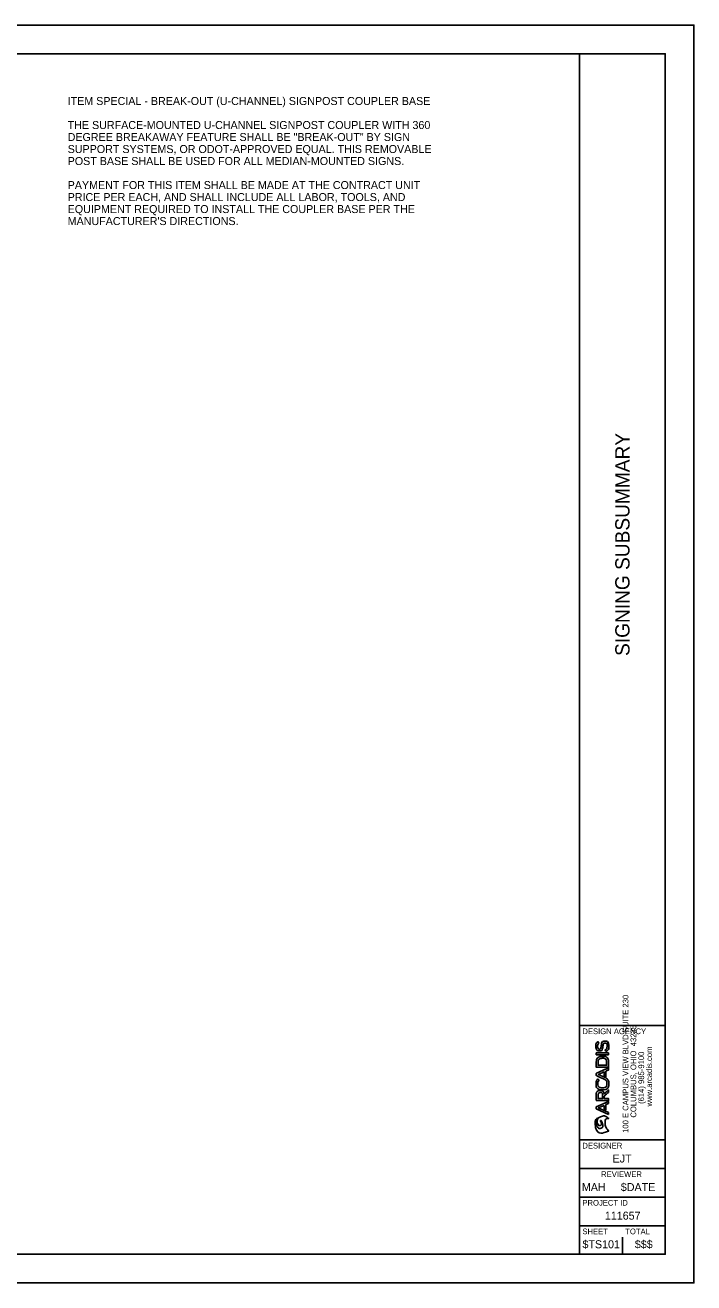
# Model space of a CAD drawing. Extents: x 0 to 34, y 0 to 22.
# Drawn here: x 22.3 to 34, y 0 to 22 of the extents above; entities that cross this region are included whole.
import ezdxf

# ---------------------------------------------------------------- set-up
doc = ezdxf.new("R2010")
doc.units = 0
for name, color, linetype in [('SH_Border', 7, 'Continuous'), ('SH_Cut_Line', 7, 'Continuous'), ('SH_Data', 7, 'Continuous'), ('SH_Text', 7, 'Continuous')]:
    doc.layers.add(name, color=color, linetype=linetype)

msp = doc.modelspace()

# ---------------------------------------------------------------- linework, layer by layer
at = {"layer": 'SH_Border'}
for p, q in [((32, 0.5), (32, 21.5)), ((32, 4.5), (33.5, 4.5)), ((32, 2.5), (33.5, 2.5)), ((32, 2), (33.5, 2)), ((32, 1.5), (33.5, 1.5)), ((32, 1), (33.5, 1))]:
    msp.add_line(p, q, dxfattribs=at)
msp.add_lwpolyline([(1.5, 21.5), (33.5, 21.5), (33.5, 0.5), (1.5, 0.5)], close=True, dxfattribs=at)
at = {"layer": 'SH_Cut_Line'}
msp.add_lwpolyline([(0, 0), (34, 0), (34, 22), (0, 22)], close=True, dxfattribs=at)
at = {"layer": 'SH_Data'}
for p, q in [((32.507, 4.022), (32.292, 4.022)), ((32.292, 4.022), (32.292, 3.988)), ((32.292, 3.988), (32.507, 3.988)), ((32.507, 3.988), (32.507, 4.022)), ((32.75, 3.5), (32.75, 3.5)), ((32.75, 3.5), (32.75, 3.5)), ((32.507, 3.175), (32.292, 3.079)), ((32.328, 3.06), (32.431, 3.105)), ((32.431, 3.105), (32.431, 3.034)), ((32.462, 3.119), (32.507, 3.139)), ((32.462, 3.02), (32.462, 3.119)), ((32.507, 3.139), (32.507, 3.175)), ((32.292, 3.079), (32.292, 3.041)), ((32.292, 3.041), (32.507, 2.945)), ((32.507, 2.981), (32.328, 3.06)), ((32.431, 3.034), (32.462, 3.02)), ((32.507, 2.945), (32.507, 2.981)), ((32.375, 0.675), (32.375, 0.675)), ((32.75, 0.5), (32.75, 0.8))]:
    msp.add_line(p, q, dxfattribs=at)
for points, degree in [([(32.34, 4.193), (32.325, 4.183), (32.316, 4.163), (32.316, 4.14), (32.316, 4.111), (32.328, 4.09), (32.348, 4.09), (32.369, 4.09), (32.375, 4.114), (32.379, 4.143), (32.385, 4.187), (32.398, 4.229), (32.446, 4.229), (32.494, 4.229), (32.512, 4.185), (32.512, 4.14), (32.512, 4.099), (32.5, 4.067), (32.463, 4.047), (32.463, 4.047), (32.446, 4.073), (32.446, 4.073), (32.472, 4.088), (32.482, 4.115), (32.482, 4.14), (32.482, 4.166), (32.473, 4.195), (32.446, 4.195), (32.422, 4.195), (32.414, 4.17), (32.41, 4.14), (32.405, 4.097), (32.394, 4.056), (32.348, 4.056), (32.303, 4.056), (32.286, 4.1), (32.286, 4.139), (32.286, 4.17), (32.293, 4.201), (32.322, 4.22), (32.322, 4.22), (32.34, 4.193), (32.34, 4.193), (32.34, 4.193), (32.34, 4.193), (32.34, 4.193)], 3), ([(32.292, 3.772), (32.292, 3.772), (32.507, 3.772), (32.507, 3.772), (32.507, 3.772), (32.507, 3.854), (32.507, 3.854), (32.507, 3.929), (32.452, 3.963), (32.398, 3.962), (32.345, 3.961), (32.292, 3.927), (32.292, 3.854)], 3), ([(32.292, 3.664), (32.292, 3.664), (32.292, 3.626), (32.292, 3.626), (32.292, 3.626), (32.432, 3.563), (32.432, 3.563), (32.432, 3.563), (32.432, 3.563), (32.432, 3.563), (32.445, 3.557), (32.453, 3.549), (32.456, 3.547), (32.471, 3.532), (32.479, 3.51), (32.479, 3.49), (32.479, 3.434), (32.44, 3.411), (32.401, 3.41), (32.361, 3.41), (32.321, 3.435), (32.321, 3.49), (32.321, 3.51), (32.328, 3.53), (32.343, 3.545), (32.343, 3.545), (32.321, 3.569), (32.321, 3.569), (32.299, 3.547), (32.288, 3.519), (32.288, 3.49), (32.288, 3.413), (32.345, 3.376), (32.401, 3.376), (32.458, 3.376), (32.512, 3.412), (32.512, 3.49), (32.512, 3.52), (32.502, 3.549), (32.48, 3.571), (32.48, 3.571), (32.466, 3.584), (32.446, 3.593), (32.446, 3.593), (32.44, 3.596), (32.44, 3.596), (32.44, 3.596), (32.425, 3.602), (32.425, 3.602), (32.425, 3.602), (32.425, 3.602), (32.425, 3.602), (32.425, 3.602), (32.328, 3.645), (32.328, 3.645), (32.328, 3.645), (32.431, 3.69), (32.431, 3.69), (32.431, 3.69), (32.431, 3.619), (32.431, 3.619), (32.431, 3.619), (32.462, 3.605), (32.462, 3.605), (32.462, 3.605), (32.462, 3.704), (32.462, 3.704), (32.462, 3.704), (32.507, 3.724), (32.507, 3.724), (32.507, 3.724), (32.507, 3.76), (32.507, 3.76), (32.507, 3.76), (32.292, 3.664), (32.292, 3.664), (32.292, 3.664), (32.292, 3.664), (32.292, 3.664)], 3), ([(32.292, 3.854), (32.292, 3.854), (32.292, 3.772), (32.292, 3.772)], 2), ([(32.474, 3.806), (32.474, 3.806), (32.325, 3.806), (32.325, 3.806)], 2), ([(32.325, 3.806), (32.325, 3.806), (32.325, 3.854), (32.325, 3.854), (32.325, 3.905), (32.361, 3.927), (32.398, 3.928), (32.435, 3.929), (32.474, 3.906), (32.474, 3.854), (32.474, 3.854), (32.474, 3.806), (32.474, 3.806)], 3), ([(32.43, 3.305), (32.423, 3.348), (32.393, 3.364), (32.362, 3.364), (32.326, 3.364), (32.292, 3.337), (32.292, 3.288), (32.292, 3.254), (32.292, 3.221), (32.292, 3.187), (32.292, 3.187), (32.507, 3.187), (32.507, 3.187), (32.507, 3.187), (32.507, 3.222), (32.507, 3.222), (32.507, 3.222), (32.433, 3.222), (32.433, 3.222), (32.433, 3.222), (32.433, 3.267), (32.433, 3.267), (32.433, 3.267), (32.507, 3.333), (32.507, 3.333), (32.507, 3.333), (32.507, 3.373), (32.507, 3.373)], 3), ([(32.323, 3.288), (32.323, 3.316), (32.344, 3.329), (32.363, 3.329), (32.383, 3.329), (32.402, 3.316), (32.402, 3.287), (32.402, 3.287), (32.402, 3.222), (32.402, 3.222), (32.402, 3.222), (32.323, 3.222), (32.323, 3.222)], 3), ([(32.507, 3.373), (32.507, 3.373), (32.43, 3.305), (32.43, 3.305)], 2), ([(32.323, 3.222), (32.323, 3.222), (32.323, 3.288), (32.323, 3.288)], 2), ([(32.272, 2.786), (32.282, 2.575), (32.514, 2.656), (32.514, 2.656), (32.494, 2.674), (32.446, 2.734), (32.446, 2.817), (32.446, 2.817), (32.446, 2.817), (32.446, 2.818), (32.446, 2.858), (32.48, 2.881), (32.514, 2.872), (32.514, 2.872), (32.441, 2.935), (32.357, 2.9), (32.329, 2.888), (32.309, 2.857), (32.309, 2.821), (32.309, 2.808), (32.311, 2.795), (32.316, 2.782), (32.329, 2.752), (32.356, 2.748), (32.369, 2.754), (32.378, 2.759), (32.383, 2.768), (32.383, 2.777), (32.383, 2.779), (32.383, 2.781), (32.383, 2.782), (32.378, 2.813), (32.364, 2.826), (32.364, 2.833), (32.364, 2.834), (32.364, 2.835), (32.365, 2.835), (32.368, 2.84), (32.383, 2.836), (32.398, 2.796), (32.402, 2.787), (32.407, 2.769), (32.407, 2.752), (32.407, 2.732), (32.401, 2.712), (32.38, 2.706), (32.343, 2.693), (32.298, 2.738), (32.293, 2.804), (32.292, 2.807), (32.292, 2.812), (32.292, 2.815), (32.292, 2.849), (32.307, 2.873), (32.317, 2.885), (32.294, 2.871), (32.273, 2.842), (32.272, 2.796), (32.272, 2.796), (32.272, 2.792), (32.272, 2.786), (32.272, 2.786), (32.272, 2.786), (32.272, 2.786)], 3)]:
    msp.add_open_spline(points, degree=degree, dxfattribs=at)

# ---------------------------------------------------------------- texts
for s, height, p in [('SIGNING SUBSUMMARY', 0.25, (32.875, 10.966)), ('100 E CAMPUS VIEW BLVD SUITE 230', 0.1, (32.855, 2.623)), ('COLUMBUS, OHIO  43235', 0.1, (32.992, 2.89)), ('(614) 985-9100', 0.1, (33.13, 3.13)), ('www.arcadis.com', 0.1, (33.268, 3.085))]:
    msp.add_text(s, height=height, rotation=90, dxfattribs=at).set_placement(p)
for s, height, p in [('DESIGN AGENCY', 0.1, (32.05, 4.35)), ('DESIGNER', 0.1, (32.05, 2.35)), ('EJT', 0.14, (32.578, 2.105)), ('REVIEWER', 0.1, (32.378, 1.85)), ('MAH', 0.14, (32.041, 1.605)), ('$DATE', 0.14, (32.722, 1.605)), ('PROJECT ID', 0.1, (32.05, 1.35)), ('111657', 0.14, (32.443, 1.105)), ('SHEET', 0.1, (32.05, 0.85)), ('TOTAL', 0.1, (32.8, 0.85)), ('$TS101', 0.14, (32.051, 0.605)), ('$$$', 0.14, (32.967, 0.605))]:
    msp.add_text(s, height=height, dxfattribs=at).set_placement(p)
at = {"layer": 'SH_Text'}
for s, p in [('ITEM SPECIAL - BREAK-OUT (U-CHANNEL) SIGNPOST COUPLER BASE', (23.044, 20.603)), ('THE SURFACE-MOUNTED U-CHANNEL SIGNPOST COUPLER WITH 360 ', (23.044, 20.183)), ('DEGREE BREAKAWAY FEATURE SHALL BE "BREAK-OUT" BY SIGN ', (23.044, 19.973)), ('SUPPORT SYSTEMS, OR ODOT-APPROVED EQUAL. THIS REMOVABLE ', (23.044, 19.763)), ('POST BASE SHALL BE USED FOR ALL MEDIAN-MOUNTED SIGNS.', (23.044, 19.553)), ('PAYMENT FOR THIS ITEM SHALL BE MADE AT THE CONTRACT UNIT ', (23.044, 19.133)), ('PRICE PER EACH, AND SHALL INCLUDE ALL LABOR, TOOLS, AND ', (23.044, 18.923)), ('EQUIPMENT REQUIRED TO INSTALL THE COUPLER BASE PER THE ', (23.044, 18.713)), ("MANUFACTURER'S DIRECTIONS.", (23.044, 18.503))]:
    msp.add_text(s, height=0.14, dxfattribs=at).set_placement(p)

doc.saveas('drawing.dxf')
